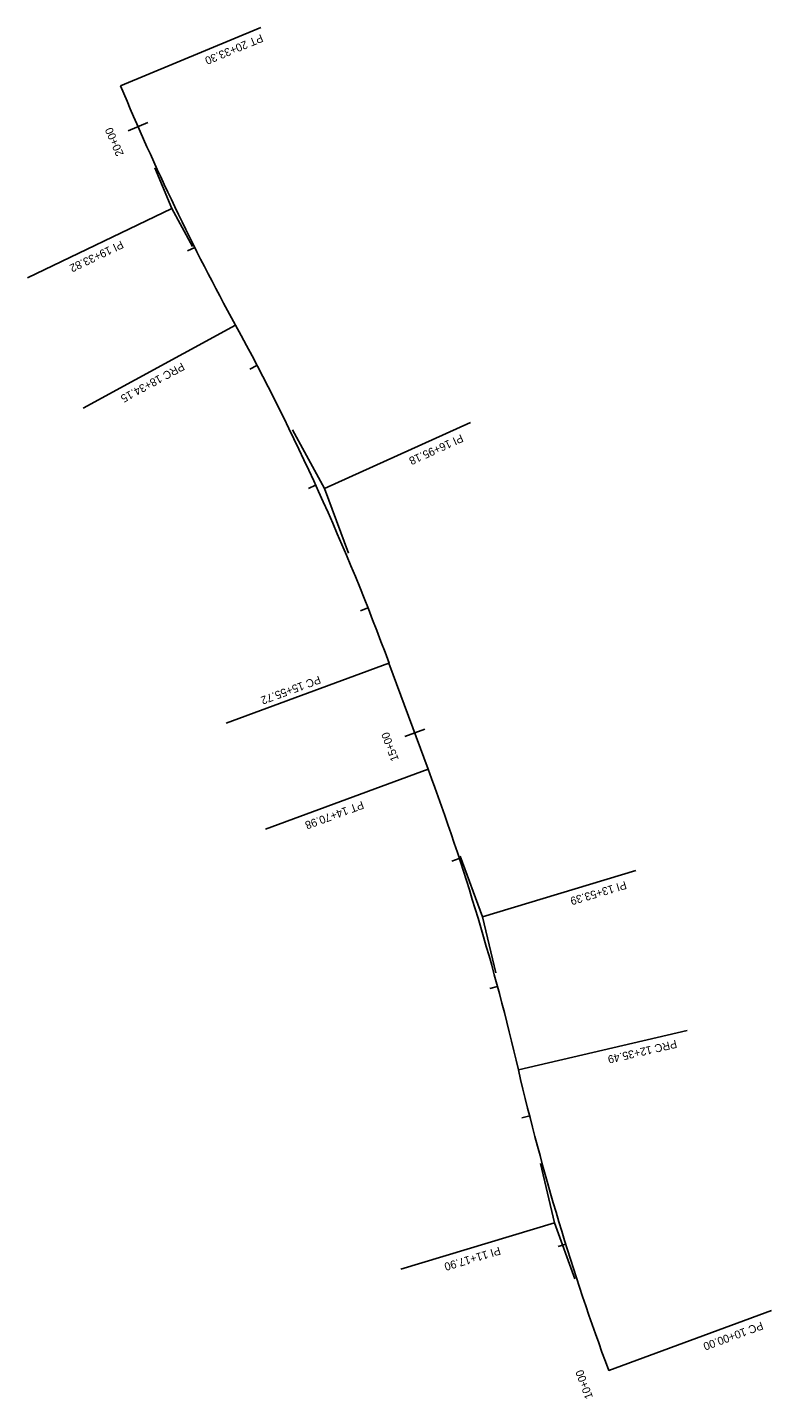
# Model space of a CAD drawing. Extents: x 955367 to 987800, y 1869413 to 1923417.
# Drawn here: x 987242 to 987800, y 1869413 to 1870441 of the extents above; entities that cross this region are included whole.
import ezdxf

# ---------------------------------------------------------------- set-up
doc = ezdxf.new("R2010")
doc.units = 0
doc.layers.add('R_Horz Alg', color=7, linetype='Continuous')
doc.layers.add('R_Horz Alg Annot', color=7, linetype='Continuous')

msp = doc.modelspace()

# ---------------------------------------------------------------- linework, layer by layer
at = {"layer": 'R_Horz Alg'}
msp.add_line((987542.3, 1869885.1), (987512.9, 1869964.6), dxfattribs=at)
for centre, start, end in [((989074.6, 1871132.4), 202.6329, 208.6071), ((985721.2, 1869303.5), 20.254, 28.6071), ((985750.5, 1869224), 13.1893, 20.254), ((989469.4, 1870095.5), 193.1893, 200.254)]:
    msp.add_arc(centre, 1909.9, start, end, dxfattribs=at)
at = {"layer": 'R_Horz Alg Annot'}
for p, q in [((987350.1, 1870305.4), (987337.4, 1870335.9)), ((987365.7, 1870277), (987350.1, 1870305.4)), ((987464.6, 1870095.5), (987440.7, 1870139.5)), ((987482.5, 1870047.1), (987464.6, 1870095.5)), ((987583.1, 1869774.5), (987566.3, 1869819.9)), ((987593, 1869732.4), (987583.1, 1869774.5)), ((987636.9, 1869545), (987626.4, 1869589.5)), ((987652.3, 1869503.1), (987636.9, 1869545))]:
    msp.add_line(p, q, dxfattribs=at)
for points in [[(987311.8, 1870397.4), (987416.8, 1870441.2)], [(987317.5, 1870363.6), (987332.2, 1870370)], [(987350.1, 1870305.4), (987241.9, 1870253.5)], [(987362, 1870273.6), (987367.3, 1870276.3)], [(987397.9, 1870217.9), (987283.7, 1870155.7)], [(987408.6, 1870185), (987413.9, 1870187.8)], [(987464.6, 1870095.5), (987573.9, 1870145.1)], [(987452.5, 1870095.5), (987457.9, 1870098)], [(987491.5, 1870003.8), (987497.1, 1870006)], [(987512.9, 1869964.6), (987391, 1869919.6)], [(987524.7, 1869909.6), (987539.7, 1869915.1)], [(987542.3, 1869885.1), (987420.3, 1869840.1)], [(987559.9, 1869816.2), (987565.6, 1869818.1)], [(987583.1, 1869774.5), (987698, 1869809.1)], [(987588.4, 1869720.7), (987594.2, 1869722.3)], [(987610, 1869659.8), (987736.5, 1869689.4)], [(987612.6, 1869623.8), (987618.4, 1869625.3)], [(987636.9, 1869545), (987521.9, 1869510.4)], [(987639.8, 1869527.3), (987645.5, 1869529)], [(987677.7, 1869434.4), (987799.6, 1869479.4)]]:
    msp.add_lwpolyline(points, dxfattribs=at)

# ---------------------------------------------------------------- texts
at = {"layer": 'R_Horz Alg'}
for rotation, p in [(112.6329, (987312.4, 1870397.2)), (118.6071, (987398.5, 1870217.8)), (110.254, (987513.5, 1869964.4)), (110.254, (987542.9, 1869884.9)), (103.1893, (987610.6, 1869659.5)), (110.254, (987678.3, 1869434.1))]:
    msp.add_text('+', height=1, rotation=rotation, dxfattribs=at).set_placement(p)
at = {"layer": 'R_Horz Alg Annot'}
for s, rotation, p in [('PT 20+33.30', 202.6329, (987417, 1870436.3)), ('20+00', 113.6317, (987314.3, 1870346.2)), ('PI 19+33.82', 205.62, (987312.1, 1870281.6)), ('PRC 18+34.15', 208.6071, (987357.6, 1870190.2)), ('PI 16+95.18', 204.4306, (987566.9, 1870136.4)), ('PC 15+55.72', 200.254, (987460.4, 1869955.4)), ('15+00', 110.254, (987520.4, 1869892.4)), ('PT 14+70.98', 200.254, (987492.7, 1869861.5)), ('PI 13+53.39', 196.7217, (987689.9, 1869801.4)), ('PRC 12+35.49', 193.1893, (987727.9, 1869682.3)), ('PI 11+17.90', 196.7217, (987595.5, 1869527.3)), ('PC 10+00.00', 200.254, (987792, 1869471.2)), ('10+00', 110.254, (987665.9, 1869414.4))]:
    msp.add_text(s, height=6, rotation=rotation, dxfattribs=at).set_placement(p)

doc.saveas('drawing.dxf')
